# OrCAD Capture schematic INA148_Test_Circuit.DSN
size A; title: INA148: ±200V Common-Mode Voltage DIFFERENCE AMPLIFIER; rev: 1.1; note: Datasheet: SBOS123  EVM : N/A
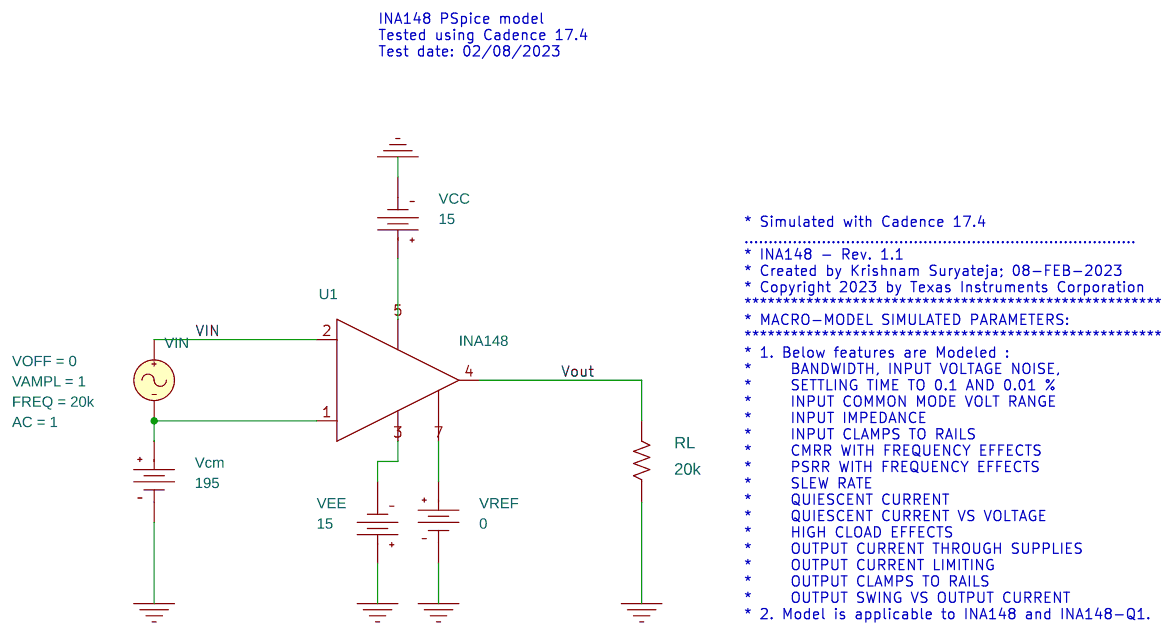
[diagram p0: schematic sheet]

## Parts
RL  20k  [AX/RC05]
U1  INA148
VCC  VDC
Vcm  VDC
VEE  VDC
VIN  VSIN
VREF  VDC

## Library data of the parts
RL = R
U1 = INA148
VCC VEE = VDC: DC: 15
Vcm = VDC: DC: 195
VIN = VSIN: AC: 1; FREQ: 20k; VAMPL: 1; VOFF: 0
VREF = VDC: DC: 0

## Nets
VIN: U1.2(-) VIN.1(+)
0: RL.1 VCC.1(-) Vcm.1(-) VEE.0(+) VREF.1(-)
Vout: RL.2 U1.4(OUT)
N14296625: U1.1(+) Vcm.0(+) VIN.2(-)
N14302073: U1.3(V-) VEE.1(-)
N14302091: U1.5(V+) VCC.0(+)
N14302143: U1.7(REF) VREF.0(+)

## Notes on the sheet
- INA148 PSpice model
  Tested using Cadence 17.4
  Test date: 02/08/2023
- * Simulated with Cadence 17.4
  .................................................................................
  * INA148 - Rev. 1.1
  * Created by Krishnam Suryateja; 08-FEB-2023
  * Copyright 2023 by Texas Instruments Corporation
  ******************************************************
  * MACRO-MODEL SIMULATED PARAMETERS:
  ******************************************************
  * 1. Below features are Modeled :
  *     BANDWIDTH, INPUT VOLTAGE NOISE,
  *     SETTLING TIME TO 0.1 AND 0.01 %
  *     INPUT COMMON MODE VOLT RANGE
  *     INPUT IMPEDANCE
  *     INPUT CLAMPS TO RAILS
  *     CMRR WITH FREQUENCY EFFECTS
  *     PSRR WITH FREQUENCY EFFECTS
  *     SLEW RATE
  *     QUIESCENT CURRENT
  *     QUIESCENT CURRENT VS VOLTAGE
  *     HIGH CLOAD EFFECTS
  *     OUTPUT CURRENT THROUGH SUPPLIES
  *     OUTPUT CURRENT LIMITING
  *     OUTPUT CLAMPS TO RAILS
  *     OUTPUT SWING VS OUTPUT CURRENT
  * 2. Model is applicable to INA148 and INA148-Q1.
